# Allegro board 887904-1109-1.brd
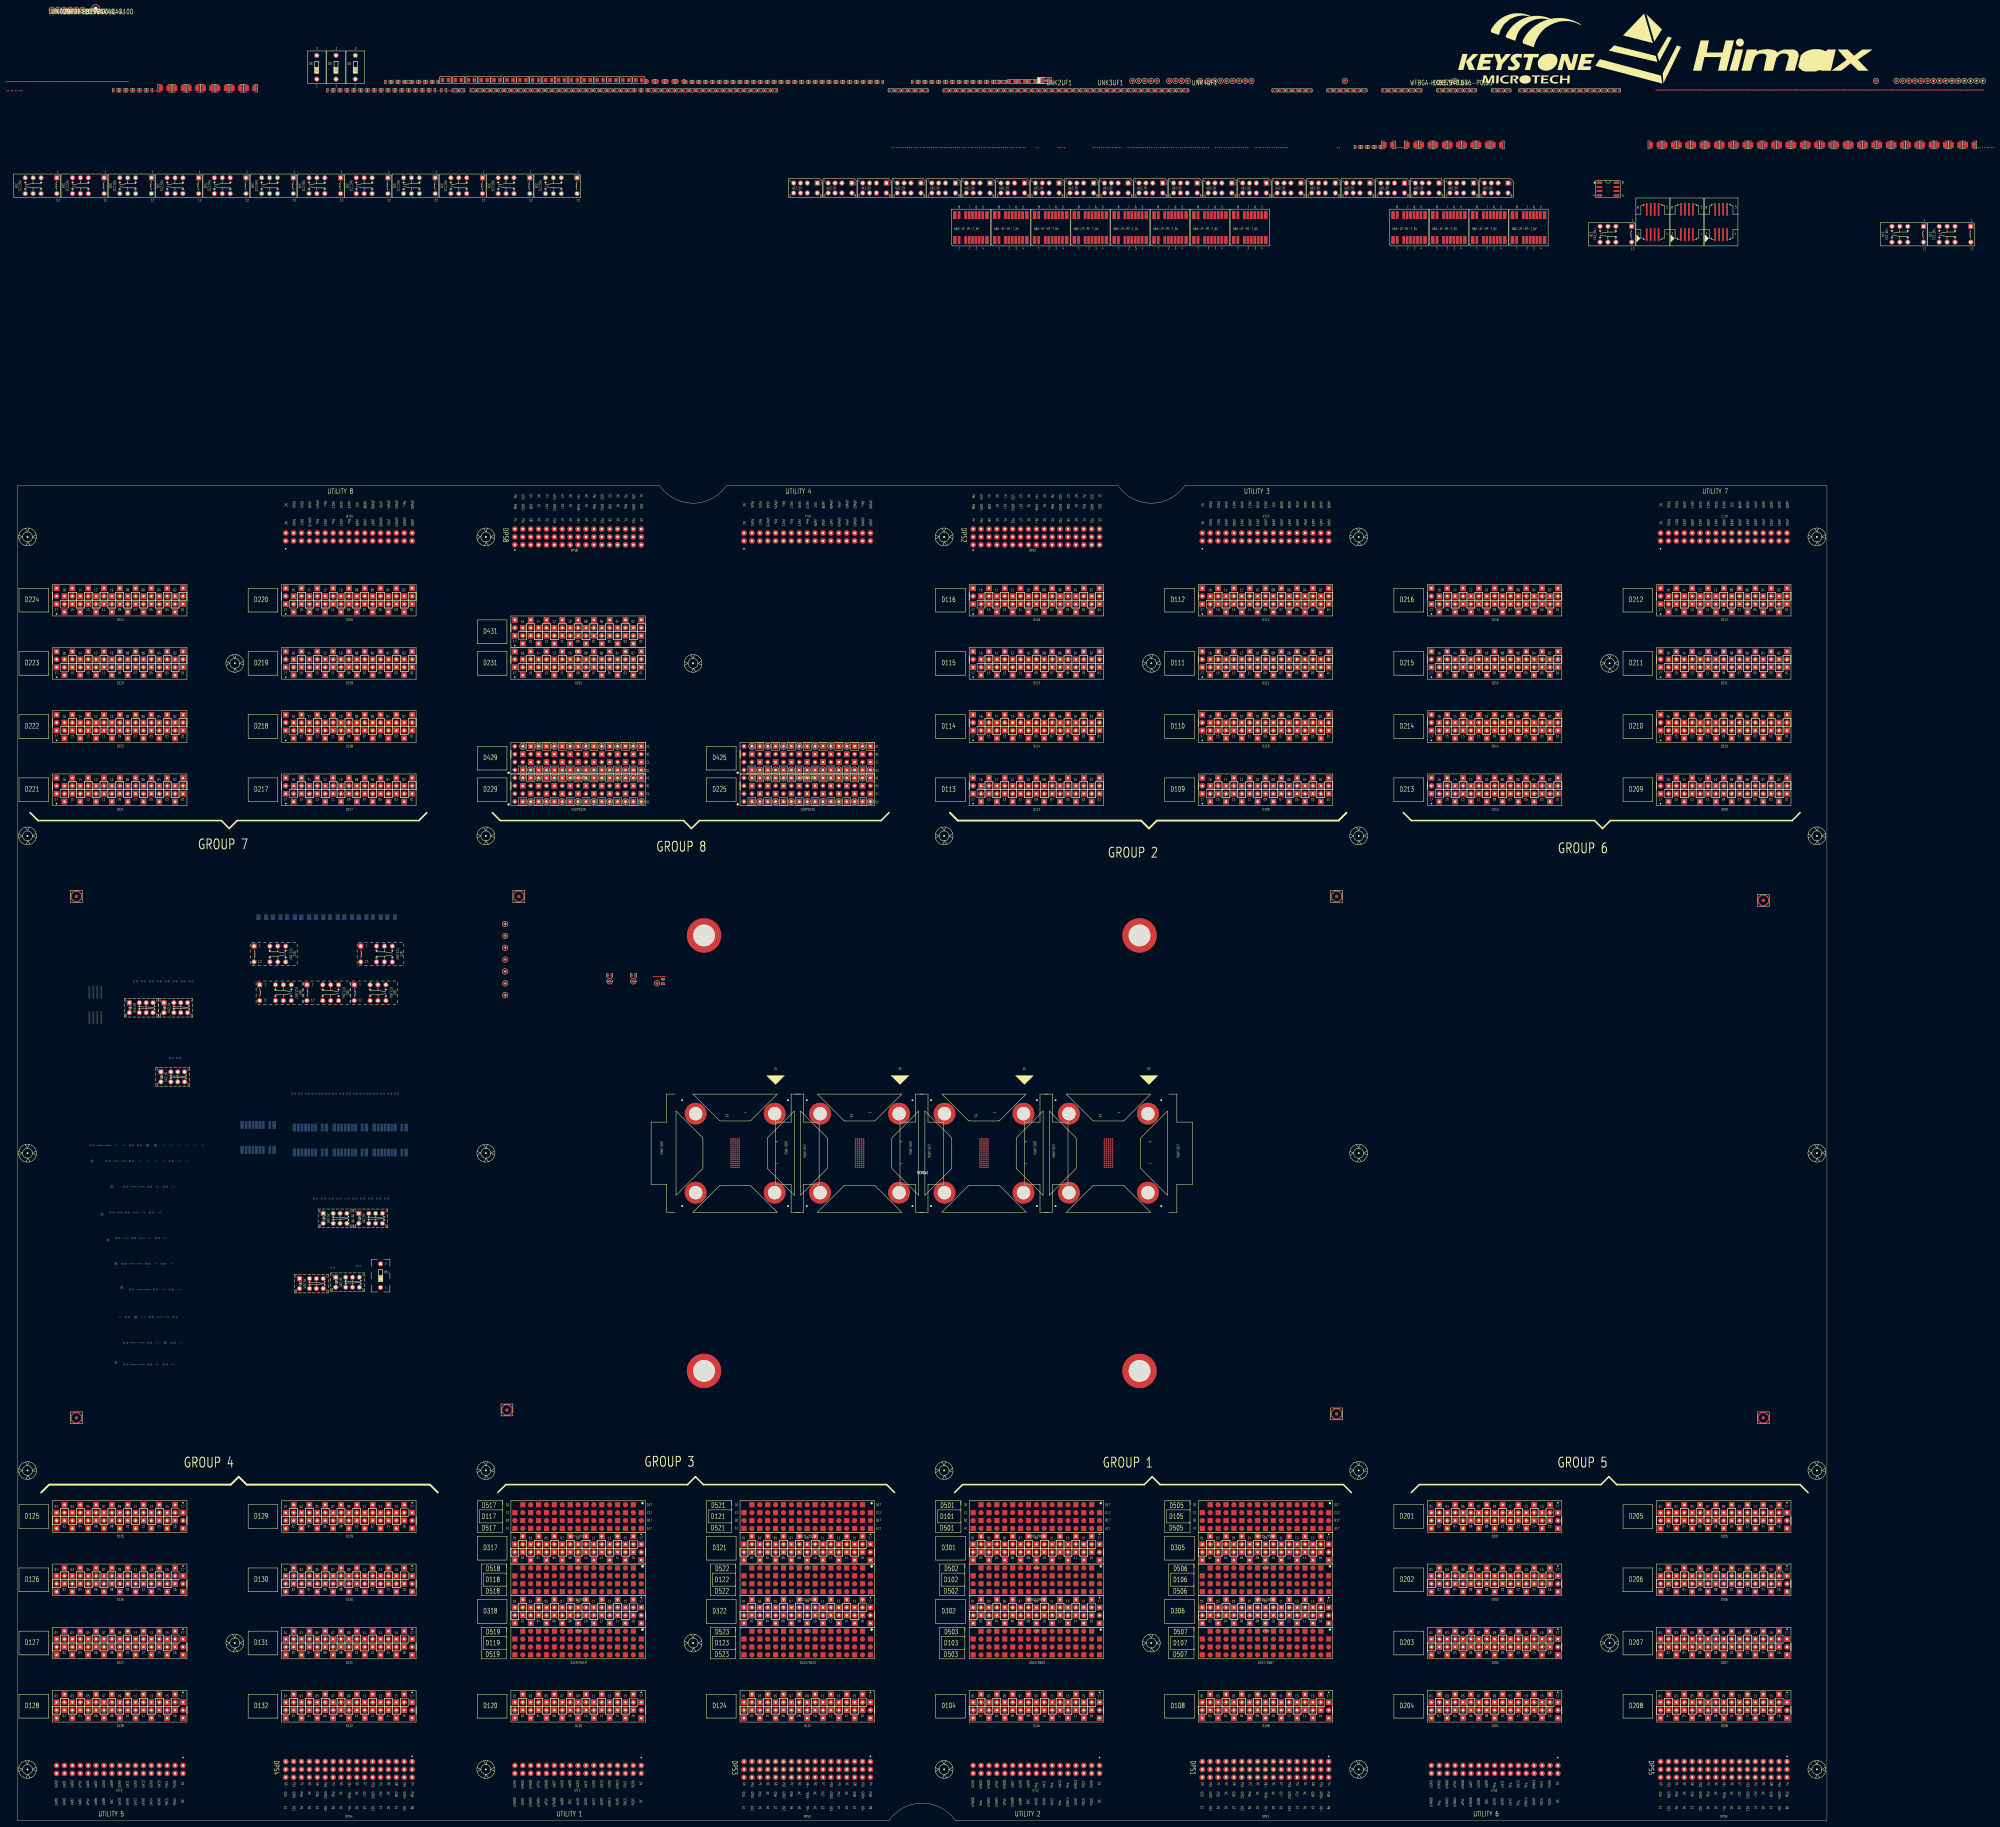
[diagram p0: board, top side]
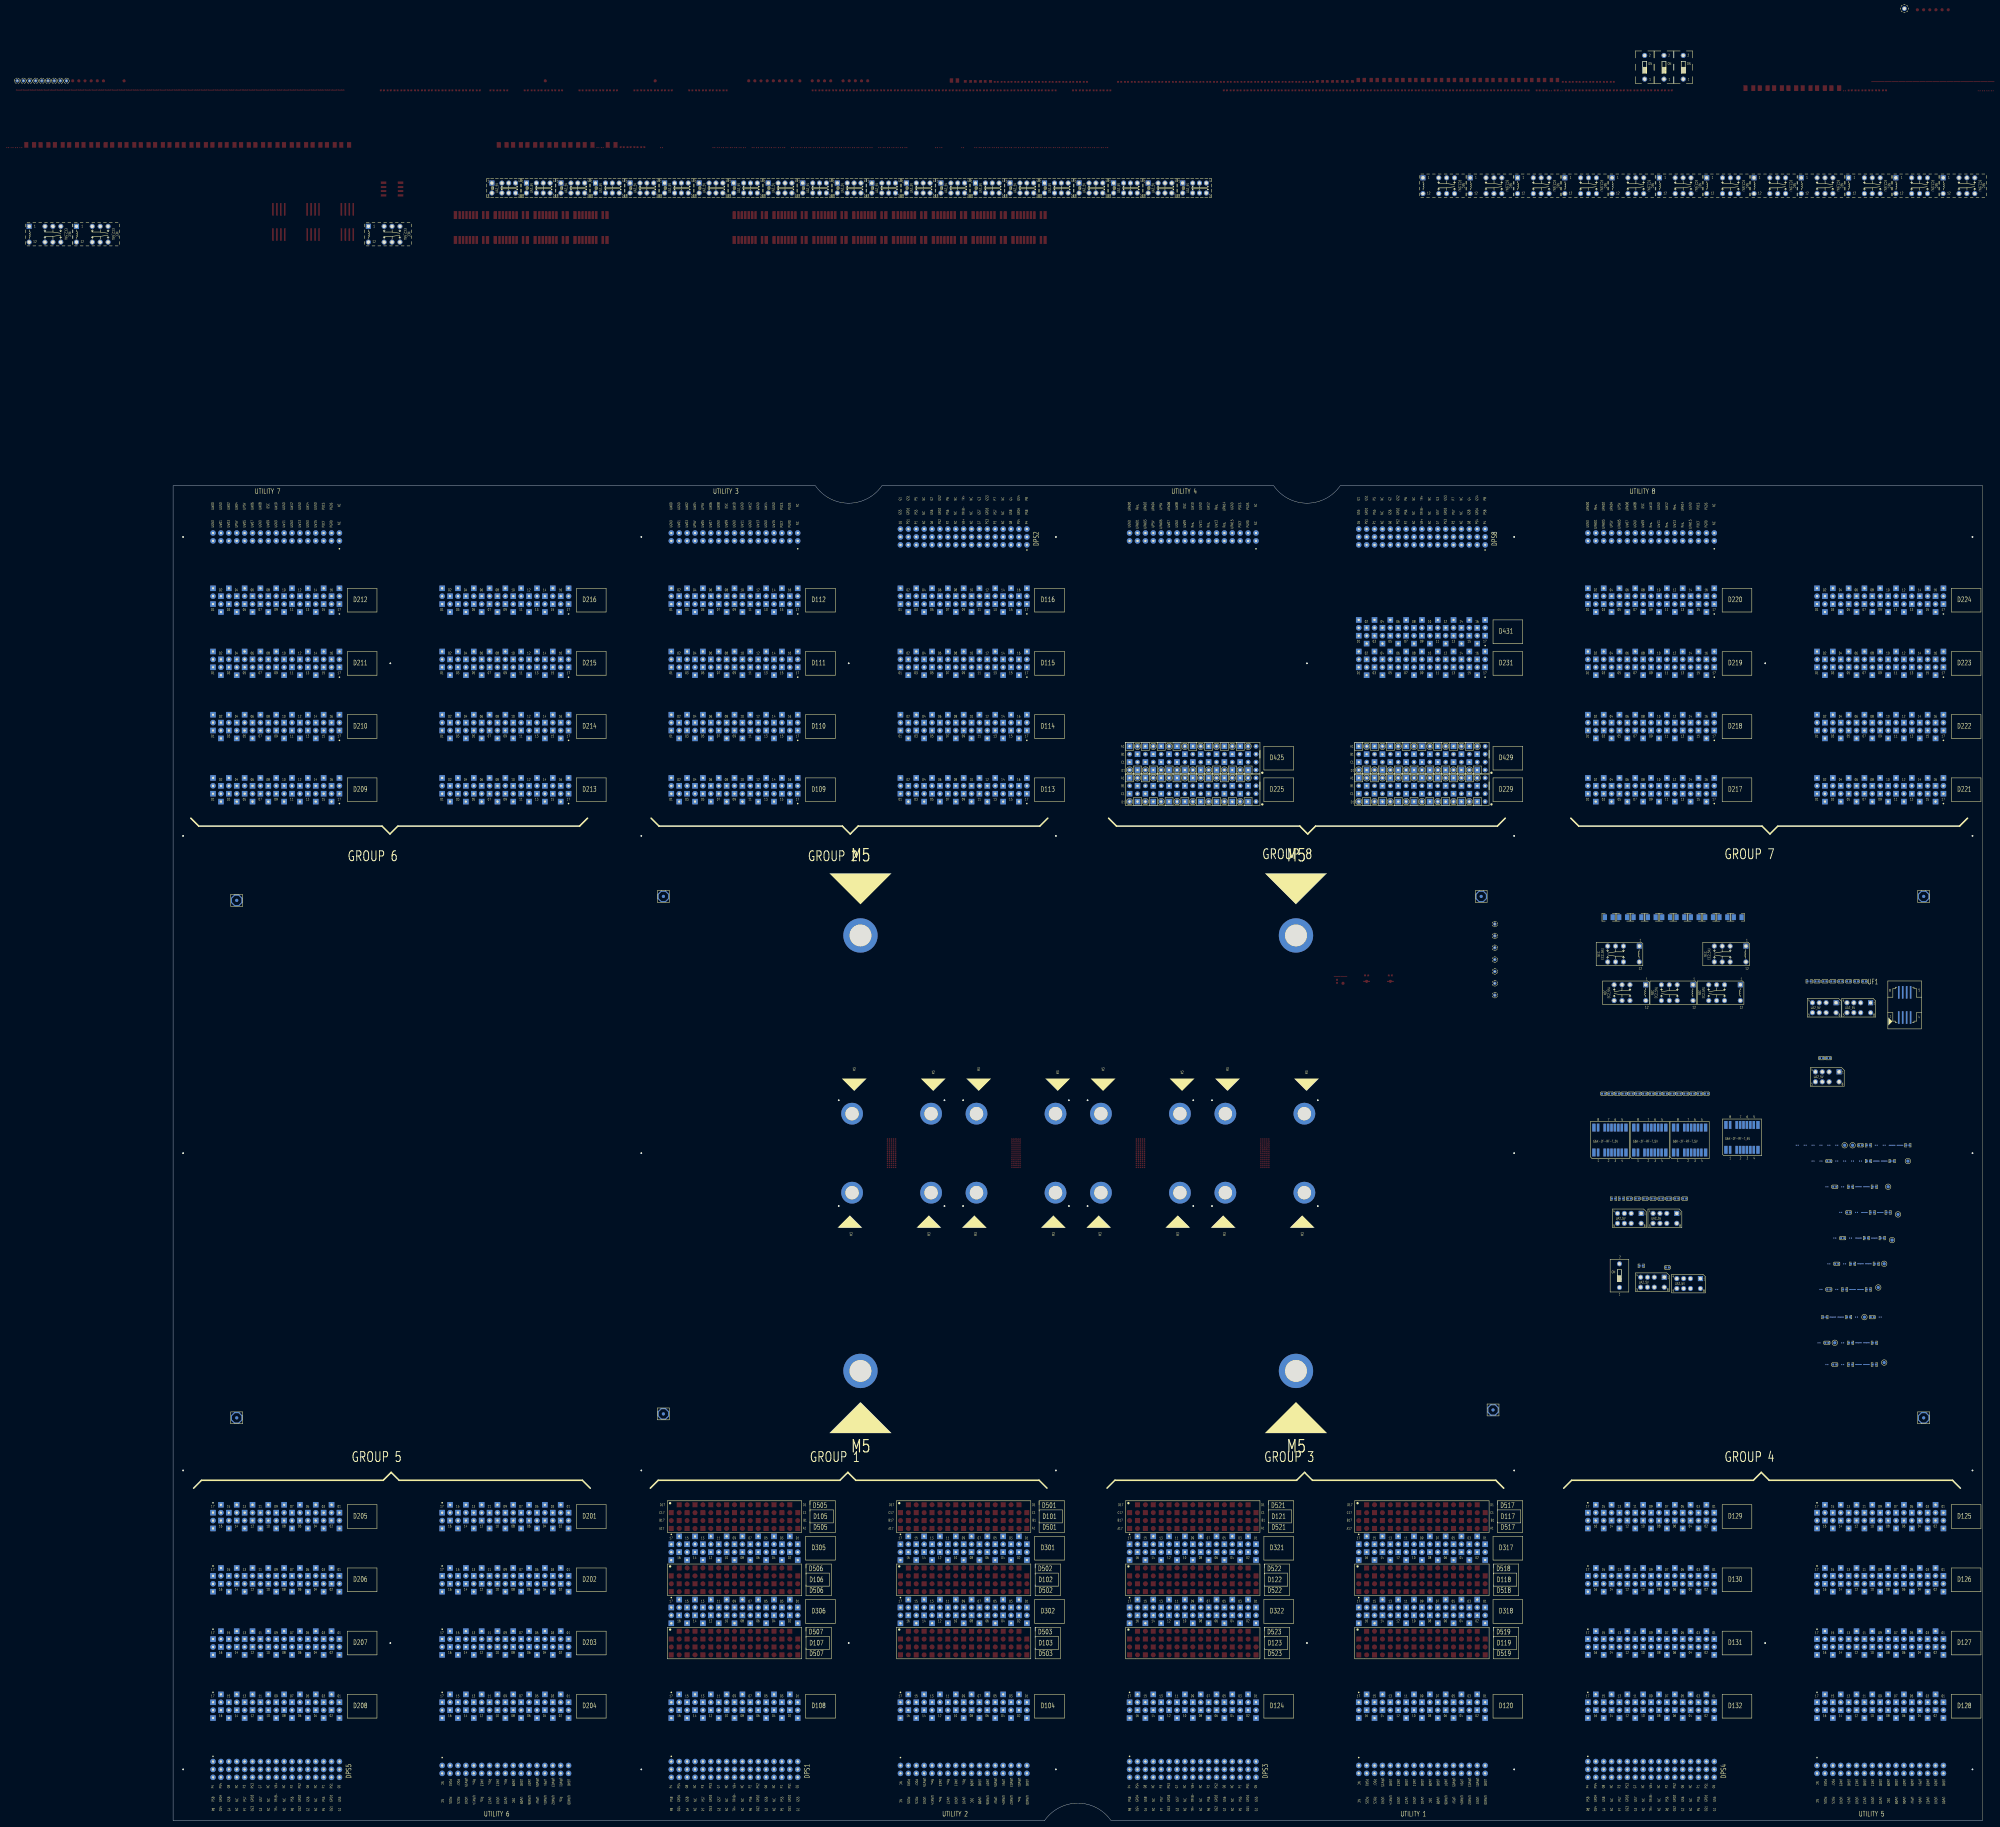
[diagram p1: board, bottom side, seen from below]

Outline 581.66 x 429.26 mm; copper layers: TOP, L02_GND, L03_SIGNAL, L04_GND, L05_SIGNAL, L06_GND, L07_SIGNAL, L08_GND, L09_POWER, L10_GND, L11_POWER, L12_GND, L13_POWER, L14_GND, L15_POWER, L16_GND, L17_POWER, L18_GND, L19_POWER, L20_GND, L21_POWER, L22_GND, L23_POWER, L24_GND, L25_5V, L26_CBIT, L27_GND, L28_SIGNAL, L29_GND, L30_SIGNAL, L31_GND, L32_SIGNAL, L33_GND, BOTTOM. Coordinates in mm from the lower left corner of the outline.

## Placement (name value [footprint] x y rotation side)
BD29  BD120-3A-S8  [FB0805]  137.61 559.64 0 top
BD30  BD120-3A-S8  [FB0805]  141.75 559.64 0 top
BD31  BD120-3A-S8  [FB0805]  145.89 559.64 0 top
BD32  BD120-3A-S8  [FB0805]  150.03 559.64 0 top
BD33  BD120-3A-S8  [FB0805]  154.17 559.64 0 top
BD34  BD120-3A-S8  [FB0805]  158.31 559.64 0 top
BD35  BD120-3A-S8  [FB0805]  162.45 559.64 0 top
BD36  BD120-3A-S8  [FB0805]  166.59 559.64 0 top
BD37  BD120-3A-S8  [FB0805]  170.73 559.64 0 top
BD38  BD120-3A-S8  [FB0805]  174.87 559.64 0 top
BD39  BD120-3A-S8  [FB0805]  179.01 559.64 0 top
BD40  BD120-3A-S8  [FB0805]  183.15 559.64 0 top
BD41  BD120-3A-S8  [FB0805]  187.29 559.64 0 top
BD42  BD120-3A-S8  [FB0805]  191.43 559.64 0 top
BD43  BD120-3A-S8  [FB0805]  195.57 559.64 0 top
BD44  BD120-3A-S8  [FB0805]  199.71 559.64 0 top
C1  0.1U-16-X-S4-MU  [C0402]  55.75 269.88 180 bottom
C53  0.1U-16-X-S4-MU  [C0402]  116.07 200.03 180 bottom
C54  0.1U-16-X-S4-MU  [C0402]  118.61 200.03 180 bottom
C55  0.1U-16-X-S4-MU  [C0402]  109.72 178.44 180 bottom
C67  1U-10-X-S4-MU  [C0402]  36.7 217.17 180 bottom
C69  10U-25-X7R-SA  [C1206]  78.7 290.49 180 bottom
C70  10U-25-X7R-SA  [C1206]  83.3 290.49 180 bottom
C71  1U-10-X-S4-MU  [C0402]  36.7 212.09 180 bottom
C73  1U-10-X-S4-MU  [C0402]  42.41 203.84 180 bottom
C75  1U-10-X-S4-MU  [C0402]  35.43 195.58 180 bottom
C77  1U-10-X-S4-MU  [C0402]  37.33 187.32 180 bottom
C79  1U-10-X-S4-MU  [C0402]  41.78 179.07 180 bottom
C81  1U-10-X-S4-MU  [C0402]  44.32 170.81 180 bottom
C83  1U-10-X-S4-MU  [C0402]  43.05 161.93 180 bottom
C85  1U-10-X-S4-MU  [C0402]  42.41 153.67 180 bottom
C87  1U-10-X-S4-MU  [C0402]  42.41 146.69 180 bottom
C89  10U-25-X7R-SA  [C1206]  87.91 290.49 180 bottom
C90  10U-25-X7R-SA  [C1206]  92.51 290.49 180 bottom
C91  10U-25-X7R-SA  [C1206]  97.11 290.49 180 bottom
C92  10U-25-X7R-SA  [C1206]  101.72 290.49 180 bottom
C93  10U-25-X7R-SA  [C1206]  106.32 290.49 180 bottom
C94  10U-25-X7R-SA  [C1206]  110.92 290.49 180 bottom
C95  10U-25-X7R-SA  [C1206]  115.53 290.49 180 bottom
C96  10U-25-X7R-SA  [C1206]  120.13 290.49 180 bottom
CA1  NC/2.2U-10-X-S4-MU  [C0402]  24 217.17 180 bottom
CA2  NC/2.2U-10-X-S4-MU  [C0402]  29.08 212.09 180 bottom
CA3  NC/2.2U-10-X-S4-MU  [C0402]  34.79 203.84 180 bottom
CA4  NC/2.2U-10-X-S4-MU  [C0402]  30.35 195.58 180 bottom
CA5  NC/2.2U-10-X-S4-MU  [C0402]  32.25 187.32 180 bottom
CA6  NC/2.2U-10-X-S4-MU  [C0402]  34.16 179.07 180 bottom
CA7  NC/2.2U-10-X-S4-MU  [C0402]  36.7 170.81 180 bottom
CA8  NC/2.2U-10-X-S4-MU  [C0402]  50.67 161.93 180 bottom
CA9  NC/2.2U-10-X-S4-MU  [C0402]  34.79 153.67 180 bottom
CA10  NC/2.2U-10-X-S4-MU  [C0402]  34.79 146.69 180 bottom
CA12  NC/2.2U-10-X-S4-MU  [C0402]  207.51 269.88 90 top
CA13  NC/2.2U-10-X-S4-MU  [C0402]  190.37 271.78 0 top
CA14  NC/2.2U-10-X-S4-MU  [C0402]  197.99 271.78 0 top
CB1  0.1U-16-X-S4-MU  [C0402]  277.38 559.05 0 top
CB2  10U-25-X7R-SA  [C1206]  457.3 538.78 0 top
CB3  0.1U-16-X-S4-MU  [C0402]  272.98 559.05 0 top
CB4  10U-25-X7R-SA  [C1206]  452.7 538.78 0 top
CB5  0.1U-16-X-S4-MU  [C0402]  270.77 559.05 0 top
CB6  10U-25-X7R-SA  [C1206]  448.09 538.78 0 top
CB7  0.1U-16-X-S4-MU  [C0402]  268.57 559.05 0 top
CB8  10U-25-X7R-SA  [C1206]  440.68 538.78 0 top
CB9  0.1U-25-X-S6  [C0603]  212.99 559.2 0 top
CB10  10U-25-X7R-SA  [C1206]  475.71 538.78 0 top
CB11  0.1U-25-X-S6  [C0603]  203.38 559.2 0 top
CB12  10U-25-X7R-SA  [C1206]  471.11 538.78 0 top
CB13  0.1U-25-X-S6  [C0603]  206.58 559.2 0 top
CB14  10U-25-X7R-SA  [C1206]  466.5 538.78 0 top
CB15  0.1U-25-X-S6  [C0603]  209.79 559.2 0 top
CB16  10U-25-X7R-SA  [C1206]  461.9 538.78 0 top
CB19  0.1U-16-X-S4-MU  [C0402]  275.18 559.05 0 top
CC1  0.47U-10-X6S-S2-TY  [C0201]  31.62 217.17 180 bottom
CC2  0.47U-10-X6S-S2-TY  [C0201]  46.86 217.17 180 bottom
CC3  0.47U-10-X6S-S2-TY  [C0201]  49.4 217.17 180 bottom
CC4  0.47U-10-X6S-S2-TY  [C0201]  34.16 217.17 180 bottom
CC5  0.47U-10-X6S-S2-TY  [C0201]  46.86 212.09 180 bottom
CC6  0.47U-10-X6S-S2-TY  [C0201]  41.78 212.09 180 bottom
CC7  0.47U-10-X6S-S2-TY  [C0201]  44.32 212.09 180 bottom
CC8  0.47U-10-X6S-S2-TY  [C0201]  44.95 203.84 180 bottom
CC9  0.47U-10-X6S-S2-TY  [C0201]  40.51 195.58 180 bottom
CC10  0.47U-10-X6S-S2-TY  [C0201]  42.41 187.32 180 bottom
CC11  0.47U-10-X6S-S2-TY  [C0201]  44.32 179.07 180 bottom
CC12  0.47U-10-X6S-S2-TY  [C0201]  46.86 170.81 180 bottom
CC13  0.47U-10-X6S-S2-TY  [C0201]  40.51 161.93 180 bottom
CC14  0.47U-10-X6S-S2-TY  [C0201]  44.95 153.67 180 bottom
CC15  0.47U-10-X6S-S2-TY  [C0201]  44.95 146.69 180 bottom
CD1  0.1U-10-X7R-S2-MU  [C0201]  51.94 217.17 180 bottom
CD2  0.1U-10-X7R-S2-MU  [C0201]  54.48 217.17 180 bottom
CD3  0.1U-10-X7R-S2-MU  [C0201]  57.02 217.17 180 bottom
CD4  0.1U-10-X7R-S2-MU  [C0201]  59.56 217.17 180 bottom
CD5  0.1U-10-X7R-S2-MU  [C0201]  51.94 212.09 180 bottom
CD6  0.1U-10-X7R-S2-MU  [C0201]  39.24 212.09 180 bottom
CD7  0.1U-10-X7R-S2-MU  [C0201]  54.48 212.09 180 bottom
CD8  0.1U-10-X7R-S2-MU  [C0201]  50.03 203.84 180 bottom
CD9  0.1U-10-X7R-S2-MU  [C0201]  45.59 195.58 180 bottom
CD10  0.1U-10-X7R-S2-MU  [C0201]  47.49 187.32 180 bottom
CD11  0.1U-10-X7R-S2-MU  [C0201]  49.4 179.07 180 bottom
CD12  0.1U-10-X7R-S2-MU  [C0201]  51.94 170.81 180 bottom
CD13  0.1U-10-X7R-S2-MU  [C0201]  32.89 161.93 180 bottom
CD14  0.1U-10-X7R-S2-MU  [C0201]  52.57 153.67 180 bottom
CD15  0.1U-10-X7R-S2-MU  [C0201]  50.03 146.69 180 bottom
CSDPS225  V93K_CSDPS_DPS32  [PG_VG93K_PF_DPS32_G8D225]  253.87 331.47 0 top
CSDPS229  V93K_CSDPS_DPS32  [PG_VG93K_PF_DPS32_G8D229]  180.21 331.47 0 top
CSDPS425  V93K_CSDPS_DPS32  [PG_VG93K_PF_DPS32_G8D425]  253.87 341.63 0 top
CSDPS429  V93K_CSDPS_DPS32  [PG_VG93K_PF_DPS32_G8D429]  180.21 341.63 0 top
D101/D501  V93K_PS1600 HD  [PG_VG93K_F_HSM_G1D101_501_ND]  327.53 97.79 0 top
D102/D502  V93K_PS1600 HD  [PG_VG93K_F_HSM_G1D102_502_ND]  327.53 77.47 0 top
D103/D503  V93K_PS1600 HD  [PG_VG93K_F_HSM_G1D103_503_ND]  327.53 57.15 0 top
D104  V93K_CH  [PG_VG93K_F_G1D104]  327.53 36.83 0 top
D105/D505  V93K_PS1600 HD  [PG_VG93K_F_HSM_G1D105_505_ND]  401.19 97.79 0 top
D106/D506  V93K_PS1600 HD  [PG_VG93K_F_HSM_G1D106_506_ND]  401.19 77.47 0 top
D107/D507  V93K_PS1600 HD  [PG_VG93K_F_HSM_G1D107_507_ND]  401.19 57.15 0 top
D108  V93K_CH  [PG_VG93K_F_G1D108]  401.19 36.83 0 top
D109  V93K_CH  [PG_VG93K_F_G2D109]  401.19 331.47 0 top
D110  V93K_CH  [PG_VG93K_F_G2D110]  401.19 351.79 0 top
D111  V93K_CH  [PG_VG93K_F_G2D111]  401.19 372.11 0 top
D112  V93K_CH  [PG_VG93K_F_G2D112]  401.19 392.43 0 top
D113  V93K_CH  [PG_VG93K_F_G2D113]  327.53 331.47 0 top
D114  V93K_CH  [PG_VG93K_F_G2D114]  327.53 351.79 0 top
D115  V93K_CH  [PG_VG93K_F_G2D115]  327.53 372.11 0 top
D116  V93K_CH  [PG_VG93K_F_G2D116]  327.53 392.43 0 top
D117/D517  V93K_PS1600 HD  [PG_VG93K_F_HSM_G3D117_517_ND]  180.21 97.79 0 top
D118/D518  V93K_PS1600 HD  [PG_VG93K_F_HSM_G3D118_518_ND]  180.21 77.47 0 top
D119/D519  V93K_PS1600 HD  [PG_VG93K_F_HSM_G3D119_519_ND]  180.21 57.15 0 top
D120  V93K_CH  [PG_VG93K_F_G3D120]  180.21 36.83 0 top
D121/D521  V93K_PS1600 HD  [PG_VG93K_F_HSM_G3D121_521_ND]  253.87 97.79 0 top
D122/D522  V93K_PS1600 HD  [PG_VG93K_F_HSM_G3D122_522_ND]  253.87 77.47 0 top
D123/D523  V93K_PS1600 HD  [PG_VG93K_F_HSM_G3D123_523_ND]  253.87 57.15 0 top
D124  V93K_CH  [PG_VG93K_F_G3D124]  253.87 36.83 0 top
D125  V93K_CH  [PG_VG93K_F_G4D125]  32.89 97.79 0 top
D126  V93K_CH  [PG_VG93K_F_G4D126]  32.89 77.47 0 top
D127  V93K_CH  [PG_VG93K_F_G4D127]  32.89 57.15 0 top
D128  V93K_CH  [PG_VG93K_F_G4D128]  32.89 36.83 0 top
D129  V93K_CH  [PG_VG93K_F_G4D129]  106.55 97.79 0 top
D130  V93K_CH  [PG_VG93K_F_G4D130]  106.55 77.47 0 top
D131  V93K_CH  [PG_VG93K_F_G4D131]  106.55 57.15 0 top
D132  V93K_CH  [PG_VG93K_F_G4D132]  106.55 36.83 0 top
D201  V93K_CH  [PG_VG93K_F_G5D201]  474.85 97.79 0 top
D202  V93K_CH  [PG_VG93K_F_G5D202]  474.85 77.47 0 top
D203  V93K_CH  [PG_VG93K_F_G5D203]  474.85 57.15 0 top
D204  V93K_CH  [PG_VG93K_F_G5D204]  474.85 36.83 0 top
D205  V93K_CH  [PG_VG93K_F_G5D205]  548.51 97.79 0 top
D206  V93K_CH  [PG_VG93K_F_G5D206]  548.51 77.47 0 top
D207  V93K_CH  [PG_VG93K_F_G5D207]  548.51 57.15 0 top
D208  V93K_CH  [PG_VG93K_F_G5D208]  548.51 36.83 0 top
D209  V93K_CH  [PG_VG93K_F_G6D209]  548.51 331.47 0 top
D210  V93K_CH  [PG_VG93K_F_G6D210]  548.51 351.79 0 top
D211  V93K_CH  [PG_VG93K_F_G6D211]  548.51 372.11 0 top
D212  V93K_CH  [PG_VG93K_F_G6D212]  548.51 392.43 0 top
D213  V93K_CH  [PG_VG93K_F_G6D213]  474.85 331.47 0 top
D214  V93K_CH  [PG_VG93K_F_G6D214]  474.85 351.79 0 top
D215  V93K_CH  [PG_VG93K_F_G6D215]  474.85 372.11 0 top
D216  V93K_CH  [PG_VG93K_F_G6D216]  474.85 392.43 0 top
D217  V93K_CH  [PG_VG93K_F_G7D217]  106.55 331.47 0 top
D218  V93K_CH  [PG_VG93K_F_G7D218]  106.55 351.79 0 top
D219  V93K_CH  [PG_VG93K_F_G7D219]  106.55 372.11 0 top
D220  V93K_CH  [PG_VG93K_F_G7D220]  106.55 392.43 0 top
D221  V93K_CH  [PG_VG93K_F_G7D221]  32.89 331.47 0 top
D222  V93K_CH  [PG_VG93K_F_G7D222]  32.89 351.79 0 top
D223  V93K_CH  [PG_VG93K_F_G7D223]  32.89 372.11 0 top
D224  V93K_CH  [PG_VG93K_F_G7D224]  32.89 392.43 0 top
D231  V93K_CH  [PG_VG93K_F_G8D231]  180.21 372.11 0 top
D301  V93K_CH  [PG_VG93K_F_G1D301]  327.53 87.63 0 top
D302  V93K_CH  [PG_VG93K_F_G1D302]  327.53 67.31 0 top
D305  V93K_CH  [PG_VG93K_F_G1D305]  401.19 87.63 0 top
D306  V93K_CH  [PG_VG93K_F_G1D306]  401.19 67.31 0 top
D317  V93K_CH  [PG_VG93K_F_G3D317]  180.21 87.63 0 top
D318  V93K_CH  [PG_VG93K_F_G3D318]  180.21 67.31 0 top
D321  V93K_CH  [PG_VG93K_F_G3D321]  253.87 87.63 0 top
D322  V93K_CH  [PG_VG93K_F_G3D322]  253.87 67.31 0 top
D431  V93K_CH  [PG_VG93K_F_G8D431]  180.21 382.27 0 top
DPS1  V93K_DPS  [PG_VG93K_F_G1DPS1]  401.19 16.51 0 top
DPS2  V93K_DPS  [PG_VG93K_F_G2DPS2]  327.53 412.75 0 top
DPS3  V93K_DPS  [PG_VG93K_F_G3DPS3]  253.87 16.51 0 top
DPS4  V93K_DPS  [PG_VG93K_F_G4DPS4]  106.55 16.51 0 top
DPS5  V93K_DPS  [PG_VG93K_F_G5DPS5]  548.51 16.51 0 top
DPS8  V93K_DPS  [PG_VG93K_F_G8DPS8]  180.21 412.75 0 top
FD1  -  [FD_040_V2]  157.35 132.08 0 top
FD2  -  [FD_040_V2]  424.05 130.81 0 top
FD3  -  [FD_040_V2]  424.05 297.18 0 top
FD4  -  [FD_040_V2]  161.16 297.18 0 top
FD5  -  [FD_040_V2]  18.92 129.54 0 top
FD6  -  [FD_040_V2]  561.21 129.54 0 top
FD7  -  [FD_040_V2]  561.21 295.91 0 top
FD8  -  [FD_040_V2]  18.92 297.18 0 top
FD9  -  [FD_040_V2]  157.35 132.08 180 bottom
FD10  -  [FD_040_V2]  424.05 130.81 180 bottom
FD11  -  [FD_040_V2]  424.05 297.18 180 bottom
FD12  -  [FD_040_V2]  161.16 297.18 180 bottom
FD13  -  [FD_040_V2]  18.92 129.54 180 bottom
FD14  -  [FD_040_V2]  561.21 129.54 180 bottom
FD15  -  [FD_040_V2]  561.21 295.91 180 bottom
FD16  -  [FD_040_V2]  18.92 297.18 180 bottom
GND1  TP01  [TP_040_T]  41.78 217.17 180 bottom
HX8879-F04  REF-CODE-CHIP  [CHIP_CODE]  460.09 558.9 0 top
K9  UA2-5NJ-A-V3  [RL_NECUA2_5V_V3]  113.33 193.68 180 bottom
K10  UA2-5NJ-A-V3  [RL_NECUA2_5V_V3]  94.28 172.72 180 bottom
K14  UA2-5NJ-A-V3  [RL_NECUA2_5V_V3]  39.57 261.4 180 bottom
K15  UA2-5NJ-A-V3  [RL_NECUA2_5V_V3]  50.68 261.4 180 bottom
K28  UA2-5NJ-A-V3  [RL_NECUA2_5V_V3]  49.72 239.18 180 bottom
K48  UA2-5NJ-A-V3  [RL_NECUA2_5V_V3]  105.9 173.14 180 bottom
K50  UA2-5NJ-A-V3  [RL_NECUA2_5V_V3]  101.9 193.68 180 bottom
K54  G6K-2F-RF-T-5V-SPECIAL  [RL_G6K2FRT_8P_5V_GR]  77.39 219.71 180 bottom
K55  EC2-5NJ-A  [RL_NECEC2_10P_5V]  84.21 266.23 180 bottom
K56  EC2-5NJ-A  [RL_NECEC2_10P_5V]  99.41 266.23 180 bottom
K57  EC2-5NJ-A  [RL_NECEC2_10P_5V]  114.61 266.23 180 bottom
K58  EC2-5NJ-A  [RL_NECEC2_10P_5V]  82.41 278.66 180 bottom
K59  EC2-5NJ-A  [RL_NECEC2_10P_5V]  116.69 278.66 180 bottom
K60  G6K-2F-RF-T-5V-SPECIAL  [RL_G6K2FRT_8P_5V_GR]  119.82 218.85 180 bottom
K61  G6K-2F-RF-T-5V-SPECIAL  [RL_G6K2FRT_8P_5V_GR]  107.01 218.85 180 bottom
K62  G6K-2F-RF-T-5V-SPECIAL  [RL_G6K2FRT_8P_5V_GR]  94.21 218.85 180 bottom
LDB1  LDB-2-S8  [LED_0805]  330.49 559.5 0 top
LOGO1  -  [LOGO_KT_KSMT]  481.96 562.84 0 top
LOGO2  LOGO_HX_Himax  [LOGO_HX_HIMAX]  550.3 564.49 0 top
LRB1  330-1-S6  [R0603]  319.75 559.2 0 top
NOREF  -  []  529.45 508.82 90 top
NOREF#2  -  []  98.72 560.45 90 top
NOREF#3  -  []  44.65 203.84 0 top
NOREF#4  -  []  335.9 516.22 0 top
NOREF#5  -  []  33.56 217.49 0 top
NOREF#6  -  []  312.8 506.32 90 top
NOREF#7  -  []  114.62 222.85 0 top
NOREF#8  -  []  321.63 538.26 0 top
NOREF#9  -  []  317.6 508.22 0 top
NOREF#10  -  []  458.82 527.93 0 top
NOREF#11  -  []  550.66 508.32 90 top
NOREF#12  -  []  314.27 521.93 90 top
NOREF#13  -  []  359.52 538.26 0 top
NOREF#14  -  []  334.83 523.33 90 top
NOREF#15  -  []  390.18 537.62 90 top
NOREF#16  -  []  332.7 195.63 90 top
NOREF#17  -  []  41.18 212.41 0 top
NOREF#18  -  []  293.37 537.62 90 top
NOREF#19  -  []  389.82 518.12 0 top
NOREF#20  -  []  101.37 216.12 90 top
NOREF#21  -  []  393.19 538.26 0 top
NOREF#22  -  []  383.81 508.22 0 top
NOREF#23  -  []  93.2 569 0 top
NOREF#24  -  []  83.01 215.26 90 top
NOREF#25  -  []  358.11 538.26 0 top
NOREF#26  -  []  380.36 537.62 90 top
NOREF#27  -  []  31.02 216.85 90 top
NOREF#28  -  []  48.8 217.49 0 top
NOREF#29  -  []  339.75 508.22 0 top
NOREF#30  -  []  229.4 219.18 0 top
NOREF#31  -  []  81.49 215.76 90 top
NOREF#32  -  []  364.81 509.49 90 top
NOREF#33  -  []  56.72 217.17 0 top
NOREF#34  -  []  -3.74 556.52 0 top
NOREF#35  -  []  105.5 192.08 90 top
NOREF#36  -  []  272 210.08 90 top
NOREF#37  -  []  362.86 508.22 90 top
NOREF#38  -  []  442.66 526.53 0 top
NOREF#39  -  []  469.72 521.93 90 top
NOREF#40  -  []  307.22 526.53 0 top
NOREF#41  -  []  466.64 518.12 0 top
NOREF#42  -  []  312.62 523.33 90 top
NOREF#43  -  []  41.18 211.77 90 top
NOREF#44  -  []  456.33 516.22 0 top
NOREF#45  -  []  260.61 526.53 0 top
NOREF#46  -  []  381.97 538.26 0 top
NOREF#47  -  []  381.1 527.93 0 top
NOREF#48  -  []  212.14 558.75 90 top
NOREF#49  -  []  392.99 537.62 90 top
NOREF#50  -  []  328.3 516.22 0 top
NOREF#51  -  []  229.4 219.18 0 top
NOREF#52  -  []  46.26 170.49 90 top
NOREF#53  -  []  289.16 537.62 90 top
NOREF#54  -  []  425.31 521.93 90 top
NOREF#55  -  []  635.42 537.62 90 top
NOREF#56  -  []  44.65 153.67 0 top
NOREF#57  -  []  262.81 526.53 0 top
NOREF#58  -  []  345.93 523.33 90 top
NOREF#59  -  []  120.37 222.85 0 top
NOREF#60  -  []  111.61 558.5 90 top
NOREF#61  -  []  98.28 174.32 0 top
NOREF#62  -  []  315.82 537.62 90 top
NOREF#63  -  []  336.15 508.27 90 top
NOREF#64  -  []  370.54 537.62 90 top
NOREF#65  -  []  460.47 526.53 0 top
NOREF#66  -  []  257.11 526.53 0 top
NOREF#67  -  []  365.43 537.94 0 top
NOREF#68  -  []  367.7 197.63 90 top
NOREF#69  -  []  352.3 537.62 90 top
NOREF#70  -  []  463.93 516.22 0 top
NOREF#71  -  []  315.72 204.55 0 top
NOREF#72  -  []  380.86 537.94 0 top
NOREF#73  -  []  465.71 507.77 90 top
NOREF#74  -  []  321.43 537.62 90 top
NOREF#75  -  []  101.9 174.74 0 top
NOREF#76  -  []  298.32 526.53 0 top
NOREF#77  -  []  454.44 509.49 90 top
NOREF#78  -  []  286.85 537.94 0 top
NOREF#79  -  []  630.31 537.94 0 top
NOREF#80  -  []  92.56 222.85 0 top
NOREF#81  -  []  304.59 537.62 90 top
NOREF#82  -  []  293.57 538.26 0 top
NOREF#83  -  []  394.42 516.22 0 top
NOREF#84  -  []  301.35 508.22 0 top
NOREF#85  -  []  336.68 527.93 0 top
NOREF#86  -  []  458.43 508.22 0 top
NOREF#87  -  []  98.31 214.9 90 top
NOREF#88  -  []  404.95 526.53 0 top
NOREF#89  -  []  348.59 537.94 0 top
NOREF#90  -  []  357.04 526.53 0 top
NOREF#91  -  []  341.1 516.22 0 top
NOREF#92  -  []  41.81 187 90 top
NOREF#93  -  []  323.04 538.26 0 top
NOREF#94  -  []  47.19 187.32 0 top
NOREF#95  -  []  288.26 537.94 0 top
NOREF#96  -  []  309.42 526.53 0 top
NOREF#97  -  []  351.4 537.94 0 top
NOREF#98  -  []  101.81 214.85 90 top
NOREF#99  -  []  279.31 526.53 0 top
NOREF#100  -  []  401.41 537.62 90 top
NOREF#101  -  []  377.55 537.62 90 top
NOREF#102  -  []  113.47 224.75 0 top
NOREF#103  -  []  22.02 267.99 0 top
NOREF#104  -  []  480.82 521.93 90 top
NOREF#105  -  []  345.48 538.26 0 top
NOREF#106  -  []  478.51 508.77 90 top
NOREF#107  -  []  47.92 240.78 0 top
NOREF#108  -  []  317.22 537.62 90 top
NOREF#109  -  []  281.17 527.93 0 top
NOREF#110  -  []  350.89 537.62 90 top
NOREF#111  -  []  368.14 526.53 0 top
NOREF#112  -  []  442.18 508.22 0 top
NOREF#113  -  []  520.25 521.72 0 top
NOREF#114  -  []  99.4 569 0 top
NOREF#115  -  []  279.31 523.33 90 top
NOREF#116  -  []  360.72 537.62 90 top
NOREF#117  -  []  243.4 201.93 90 top
NOREF#118  -  []  280.96 521.93 90 top
NOREF#119  -  []  404.95 526.53 0 top
NOREF#120  -  []  395.79 537.62 90 top
NOREF#121  -  []  480.04 509.49 90 top
NOREF#122  -  []  632.82 538.26 0 top
NOREF#123  -  []  81.14 215.71 0 top
NOREF#124  -  []  303.37 527.93 0 top
NOREF#125  -  []  528.65 508.32 90 top
NOREF#126  -  []  373.34 537.62 90 top
NOREF#127  -  []  102.4 559.94 90 top
NOREF#128  -  []  374.31 516.22 0 top
NOREF#129  -  []  343.2 508.22 0 top
NOREF#130  -  []  337.25 508.22 90 top
NOREF#131  -  []  484.04 516.22 0 top
NOREF#132  -  []  108.08 195.83 0 top
NOREF#133  -  []  347.79 527.93 0 top
NOREF#134  -  []  97.9 195.27 0 top
NOREF#135  -  []  75.74 223.71 0 top
NOREF#136  -  []  302.7 516.22 0 top
NOREF#137  -  []  25.65 266.34 0 top
NOREF#138  -  []  440.46 526.53 0 top
NOREF#139  -  []  109.33 195.27 0 top
NOREF#140  -  []  362.12 537.62 90 top
NOREF#141  -  []  118.17 222.85 0 top
NOREF#142  -  []  44.02 212.09 0 top
NOREF#143  -  []  357.01 537.94 0 top
NOREF#144  -  []  316.02 538.26 0 top
NOREF#145  -  []  33.86 217.17 0 top
NOREF#146  -  []  309.4 219.18 0 top
NOREF#147  -  []  109.9 174.74 0 top
NOREF#148  -  []  475.97 526.53 0 top
NOREF#149  -  []  346.89 538.26 0 top
NOREF#150  -  []  327.24 538.26 0 top
NOREF#151  -  []  400 537.62 90 top
NOREF#152  -  []  54.18 212.09 0 top
NOREF#153  -  []  389.61 506.32 90 top
NOREF#154  -  []  392.09 537.94 0 top
NOREF#155  -  []  293.87 537.94 0 top
NOREF#156  -  []  400.51 537.94 0 top
NOREF#157  -  []  208.94 558.75 90 top
NOREF#158  -  []  389.89 204.16 90 top
NOREF#159  -  []  93.68 567.05 0 top
NOREF#160  -  []  347.19 537.94 0 top
NOREF#161  -  []  117.07 214.85 0 top
NOREF#162  -  []  368.81 508.22 0 top
NOREF#163  -  []  46.56 212.09 0 top
NOREF#164  -  []  303.69 537.94 0 top
NOREF#165  -  []  111.13 560.45 90 top
NOREF#166  -  []  58.96 216.85 90 top
NOREF#167  -  []  116.71 171.45 90 top
NOREF#168  -  []  102.24 215.4 90 top
NOREF#169  -  []  318.33 526.53 0 top
NOREF#170  -  []  363.72 538.26 0 top
NOREF#171  -  []  376.15 537.62 90 top
NOREF#172  -  []  388.89 508.77 90 top
NOREF#173  -  []  376.81 506.32 90 top
NOREF#174  -  []  290.42 526.53 0 top
NOREF#175  -  []  375.66 508.22 90 top
NOREF#176  -  []  366.71 516.22 0 top
NOREF#177  -  []  253.7 231.63 0 top
NOREF#178  -  []  393.49 537.94 0 top
NOREF#179  -  []  355.1 537.62 90 top
NOREF#180  -  []  104.26 214.85 0 top
NOREF#181  -  []  249.51 526.53 0 top
NOREF#182  -  []  48.8 178.75 90 top
NOREF#183  -  []  89.03 169.72 90 top
NOREF#184  -  []  352.8 537.94 0 top
NOREF#185  -  []  361.51 516.22 0 top
NOREF#186  -  []  338.4 506.32 90 top
NOREF#187  -  []  88.56 216.12 90 top
NOREF#188  -  []  138.25 556.52 0 top
NOREF#189  -  []  337.68 508.77 90 top
NOREF#190  -  []  323.4 201.93 90 top
NOREF#191  -  []  384.95 526.53 0 top
NOREF#192  -  []  343.2 516.22 0 top
NOREF#193  -  []  456.33 516.22 0 top
NOREF#194  -  []  295.27 537.94 0 top
NOREF#195  -  []  291.06 537.94 0 top
NOREF#196  -  []  22.02 256.59 90 top
NOREF#197  -  []  41.48 212.09 0 top
NOREF#198  -  []  523.75 518.07 0 top
NOREF#199  -  []  48.88 263 0 top
NOREF#200  -  []  356.01 516.22 0 top
NOREF#201  -  []  361.76 508.27 90 top
NOREF#202  -  []  123.92 214.9 90 top
NOREF#203  -  []  71.74 216.98 90 top
NOREF#204  -  []  301.99 538.26 0 top
NOREF#205  -  []  376.09 508.77 90 top
NOREF#206  -  []  0.77 556.2 0 top
NOREF#207  -  []  353.7 537.62 90 top
NOREF#208  -  []  51.97 153.99 0 top
NOREF#209  -  []  384.77 538.26 0 top
NOREF#210  -  []  350.48 508.77 90 top
NOREF#211  -  []  74.64 215.71 0 top
NOREF#212  -  []  44.65 146.69 0 top
NOREF#213  -  []  309.3 537.94 0 top
NOREF#214  -  []  111.53 195.27 0 top
NOREF#215  -  []  324.24 537.62 90 top
NOREF#216  -  []  427.16 526.53 0 top
NOREF#217  -  []  247.86 527.93 0 top
NOREF#218  -  []  387.37 537.62 90 top
NOREF#219  -  []  292.07 521.93 90 top
NOREF#220  -  []  48.8 216.85 90 top
NOREF#221  -  []  33.56 216.85 90 top
NOREF#222  -  []  358.89 527.93 0 top
NOREF#223  -  []  376.35 538.26 0 top
NOREF#224  -  []  116.93 192.08 90 top
NOREF#225  -  []  348.2 279.63 90 top
NOREF#226  -  []  382.75 526.53 0 top
NOREF#227  -  []  284.05 537.94 0 top
NOREF#228  -  []  375.25 537.94 0 top
NOREF#229  -  []  332.29 558.5 90 top
NOREF#230  -  []  211.7 233.63 0 top
NOREF#231  -  []  378.06 537.94 0 top
NOREF#232  -  []  120.37 222.85 0 top
NOREF#233  -  []  403.3 527.93 0 top
NOREF#234  -  []  403.3 527.93 0 top
NOREF#235  -  []  287.22 526.53 0 top
NOREF#236  -  []  416.06 526.53 0 top
NOREF#237  -  []  289.66 537.94 0 top
NOREF#238  -  []  392.2 527.93 0 top
NOREF#239  -  []  109.33 195.27 0 top
NOREF#240  -  []  403.1 521.93 90 top
NOREF#241  -  []  296.68 537.94 0 top
NOREF#242  -  []  401.91 537.94 0 top
NOREF#243  -  []  340.7 217.09 90 top
NOREF#244  -  []  293.7 231.63 0 top
NOREF#245  -  []  203.7 204.63 90 top
NOREF#246  -  []  371.01 508.22 0 top
NOREF#247  -  []  389.28 537.94 0 top
NOREF#248  -  []  119.27 214.85 0 top
NOREF#249  -  []  452.48 508.22 90 top
NOREF#250  -  []  325.58 527.93 0 top
NOREF#251  -  []  412.53 273.64 0 top
NOREF#252  -  []  290.56 537.62 90 top
NOREF#253  -  []  369.99 527.93 0 top
NOREF#254  -  []  456.96 526.53 0 top
NOREF#255  -  []  304.8 508.22 0 top
NOREF#256  -  []  96.65 190.68 90 top
NOREF#257  -  []  399.92 516.22 0 top
NOREF#258  -  []  251.71 526.53 0 top
NOREF#259  -  []  283.75 538.26 0 top
NOREF#260  -  []  37.77 263 0 top
NOREF#261  -  []  397.7 537.94 0 top
NOREF#262  -  []  392.2 527.93 0 top
NOREF#263  -  []  39.91 195.9 0 top
NOREF#264  -  []  331.7 233.63 0 top
NOREF#265  -  []  407.52 537.94 0 top
NOREF#266  -  []  405.82 538.26 0 top
NOREF#267  -  []  105.4 558.5 90 top
NOREF#268  -  []  258.76 521.93 90 top
NOREF#269  -  []  314.62 538.26 0 top
NOREF#270  -  []  304.8 516.22 0 top
NOREF#271  -  []  335.66 538.26 0 top
NOREF#272  -  []  351.1 538.26 0 top
NOREF#273  -  []  371.64 526.53 0 top
NOREF#274  -  []  44.35 146.36 90 top
NOREF#275  -  []  102.3 195.27 0 top
NOREF#276  -  []  113.71 180.51 0 top
NOREF#277  -  []  412.55 526.53 0 top
NOREF#278  -  []  35.57 263 0 top
NOREF#279  -  []  282.82 526.53 0 top
NOREF#280  -  []  353.91 516.22 0 top
NOREF#281  -  []  235.72 204.55 0 top
NOREF#282  -  []  253.91 526.53 0 top
NOREF#283  -  []  105.9 195.27 0 top
NOREF#284  -  []  471.57 526.53 0 top
NOREF#285  -  []  346.68 537.62 90 top
NOREF#286  -  []  403.01 538.26 0 top
NOREF#287  -  []  377.01 518.12 0 top
NOREF#288  -  []  -2.34 556.52 0 top
NOREF#289  -  []  46.56 217.17 0 top
NOREF#290  -  []  452.9 508.77 90 top
NOREF#291  -  []  405.61 537.62 90 top
NOREF#292  -  []  365.13 538.26 0 top
NOREF#293  -  []  398.25 526.53 0 top
NOREF#294  -  []  293.92 526.53 0 top
NOREF#295  -  []  342.73 526.53 0 top
NOREF#296  -  []  203.7 224.63 0 top
NOREF#297  -  []  39.91 162.25 0 top
NOREF#298  -  []  447.51 521.93 90 top
NOREF#299  -  []  138.55 556.2 0 top
NOREF#300  -  []  44.47 241.33 0 top
NOREF#301  -  []  317.42 538.26 0 top
NOREF#302  -  []  100.1 195.27 0 top
NOREF#303  -  []  97.9 195.27 0 top
NOREF#304  -  []  327.7 197.63 90 top
NOREF#305  -  []  347.79 527.93 0 top
NOREF#306  -  []  345.93 526.53 0 top
NOREF#307  -  []  473.77 526.53 0 top
NOREF#308  -  []  364.21 518.12 0 top
NOREF#309  -  []  363.28 508.77 90 top
NOREF#310  -  []  179.7 258.63 0 top
NOREF#311  -  []  43.17 259.8 90 top
NOREF#312  -  []  338.33 526.53 0 top
NOREF#313  -  []  466.43 506.32 90 top
NOREF#314  -  []  31.02 217.49 0 top
NOREF#315  -  []  339.21 509.49 90 top
NOREF#316  -  []  59.26 217.17 0 top
NOREF#317  -  []  363.4 201.93 90 top
NOREF#318  -  []  34.32 258.4 90 top
NOREF#319  -  []  330.4 516.22 0 top
NOREF#320  -  []  104.1 174.74 0 top
NOREF#321  -  []  87.86 212.95 90 top
NOREF#322  -  []  479.17 526.53 0 top
NOREF#323  -  []  441.03 518.12 0 top
NOREF#324  -  []  309 538.26 0 top
NOREF#325  -  []  297.78 538.26 0 top
NOREF#326  -  []  46.26 211.77 90 top
NOREF#327  -  []  345.78 537.94 0 top
NOREF#328  -  []  491.31 508.77 90 top
NOREF#329  -  []  336.68 527.93 0 top
NOREF#330  -  []  313.01 537.62 90 top
NOREF#331  -  []  108.08 190.68 90 top
NOREF#332  -  []  113.73 195.27 0 top
NOREF#333  -  []  338 227.33 0 top
NOREF#334  -  []  299.18 538.26 0 top
NOREF#335  -  []  283.55 537.62 90 top
NOREF#336  -  []  354.2 537.94 0 top
NOREF#337  -  []  309.4 219.18 0 top
NOREF#338  -  []  248.7 233.63 0 top
NOREF#339  -  []  366.83 537.94 0 top
NOREF#340  -  []  363.52 537.62 90 top
NOREF#341  -  []  307.9 537.94 0 top
NOREF#342  -  []  149.7 315.13 0 top
NOREF#343  -  []  364.94 526.53 0 top
NOREF#344  -  []  38.94 212.09 0 top
NOREF#345  -  []  312 218.53 90 top
NOREF#346  -  []  423.66 523.33 90 top
NOREF#347  -  []  323.7 224.63 0 top
NOREF#348  -  []  296.38 538.26 0 top
NOREF#349  -  []  444.79 537.94 0 top
NOREF#350  -  []  135.84 555.88 90 top
NOREF#351  -  []  39.97 263 0 top
NOREF#352  -  []  464.87 526.53 0 top
NOREF#353  -  []  425.51 527.93 0 top
NOREF#354  -  []  46.26 212.41 0 top
NOREF#355  -  []  458.61 521.93 90 top
NOREF#356  -  []  51.08 263 0 top
NOREF#357  -  []  369.99 527.93 0 top
NOREF#358  -  []  368.81 516.22 0 top
NOREF#359  -  []  367.93 538.26 0 top
NOREF#360  -  []  268.21 523.33 90 top
NOREF#361  -  []  404.41 538.26 0 top
NOREF#362  -  []  269.4 219.18 0 top
NOREF#363  -  []  370.74 538.26 0 top
NOREF#364  -  []  46.26 171.14 0 top
NOREF#365  -  []  327.86 560.5 0 top
NOREF#366  -  []  243.7 224.63 0 top
NOREF#367  -  []  185.7 252.63 0 top
NOREF#368  -  []  469.92 527.93 0 top
NOREF#369  -  []  369.34 538.26 0 top
NOREF#370  -  []  45.72 240.78 0 top
NOREF#371  -  []  436.41 521.93 90 top
NOREF#372  -  []  379.46 537.94 0 top
NOREF#373  -  []  270.06 527.93 0 top
NOREF#374  -  []  362.32 538.26 0 top
NOREF#375  -  []  542.26 521.72 0 top
NOREF#376  -  []  303.17 521.93 90 top
NOREF#377  -  []  292.47 537.94 0 top
NOREF#378  -  []  407.22 538.26 0 top
NOREF#379  -  []  445.86 523.33 90 top
NOREF#380  -  []  381.61 516.22 0 top
NOREF#381  -  []  310.71 537.94 0 top
NOREF#382  -  []  46.68 263 0 top
NOREF#383  -  []  356.71 538.26 0 top
NOREF#384  -  []  314.48 527.93 0 top
NOREF#385  -  []  479.24 506.32 90 top
NOREF#386  -  []  377.76 538.26 0 top
NOREF#387  -  []  89.03 174.87 0 top
NOREF#388  -  []  425.51 527.93 0 top
NOREF#389  -  []  51.34 211.77 90 top
NOREF#390  -  []  633.12 537.94 0 top
NOREF#391  -  []  287.75 537.62 90 top
NOREF#392  -  []  328.7 233.63 0 top
NOREF#393  -  []  492.04 506.32 90 top
NOREF#394  -  []  134.64 556.52 0 top
NOREF#395  -  []  39.91 161.6 90 top
NOREF#396  -  []  311.65 508.22 90 top
NOREF#397  -  []  366.71 516.22 0 top
NOREF#398  -  []  391.79 538.26 0 top
NOREF#399  -  []  314.48 527.93 0 top
NOREF#400  -  []  348.09 537.62 90 top
NOREF#401  -  []  553.06 506.32 90 top
NOREF#402  -  []  534.74 509.97 90 top
NOREF#403  -  []  372.44 537.94 0 top
NOREF#404  -  []  465.28 508.22 90 top
NOREF#405  -  []  53.32 237.58 90 top
NOREF#406  -  []  394.59 538.26 0 top
NOREF#407  -  []  360.54 526.53 0 top
NOREF#408  -  []  258.96 527.93 0 top
NOREF#409  -  []  481.94 516.22 0 top
NOREF#410  -  []  305.02 526.53 0 top
NOREF#411  -  []  300.8 509.49 90 top
NOREF#412  -  []  106.09 567.05 0 top
NOREF#413  -  []  285.45 537.94 0 top
NOREF#414  -  []  32.29 162.25 0 top
NOREF#415  -  []  49.1 217.17 0 top
NOREF#416  -  []  101.9 174.74 0 top
NOREF#417  -  []  44.47 241.33 0 top
NOREF#418  -  []  89.01 222.85 0 top
NOREF#419  -  []  311.14 234.91 0 top
NOREF#420  -  []  -1.14 555.88 90 top
NOREF#421  -  []  305.99 537.62 90 top
NOREF#422  -  []  283.7 224.63 0 top
NOREF#423  -  []  310.2 537.62 90 top
NOREF#424  -  []  336.86 537.62 90 top
NOREF#425  -  []  77.94 223.71 0 top
NOREF#426  -  []  89.01 214.85 90 top
NOREF#427  -  []  341.1 516.22 0 top
NOREF#428  -  []  386.47 537.94 0 top
NOREF#429  -  []  -2.54 555.88 90 top
NOREF#430  -  []  362.62 537.94 0 top
NOREF#431  -  []  521.85 519.22 0 top
NOREF#432  -  []  338.6 518.12 0 top
NOREF#433  -  []  317.72 537.94 0 top
NOREF#434  -  []  211.7 228.68 45 top
NOREF#435  -  []  387.36 508.27 90 top
NOREF#436  -  []  379.24 523.33 90 top
NOREF#437  -  []  434.76 523.33 90 top
NOREF#438  -  []  351.64 526.53 0 top
NOREF#439  -  []  51.34 212.41 0 top
NOREF#440  -  []  382.27 537.94 0 top
NOREF#441  -  []  321.93 537.94 0 top
NOREF#442  -  []  453.76 526.53 0 top
NOREF#443  -  []  379.51 516.22 0 top
NOREF#444  -  []  333.7 231.63 0 top
NOREF#445  -  []  43.72 178.75 90 top
NOREF#446  -  []  373.55 538.26 0 top
NOREF#447  -  []  553.06 511.52 90 top
NOREF#448  -  []  357.91 537.62 90 top
NOREF#449  -  []  401.69 508.77 90 top
NOREF#450  -  []  45.43 258.4 90 top
NOREF#451  -  []  94.68 174.32 0 top
NOREF#452  -  []  32.29 161.6 90 top
NOREF#453  -  []  385.97 537.62 90 top
NOREF#454  -  []  364.92 537.62 90 top
NOREF#455  -  []  366.53 538.26 0 top
NOREF#456  -  []  386.17 538.26 0 top
NOREF#457  -  []  143.7 321.13 0 top
NOREF#458  -  []  282.65 537.94 0 top
NOREF#459  -  []  388.98 538.26 0 top
NOREF#460  -  []  349.44 526.53 0 top
NOREF#461  -  []  378.96 537.62 90 top
NOREF#462  -  []  436.61 527.93 0 top
NOREF#463  -  []  53.88 212.41 0 top
NOREF#464  -  []  531.25 521.72 0 top
NOREF#465  -  []  54.28 259.8 90 top
NOREF#466  -  []  96.65 195.83 0 top
NOREF#467  -  []  445.63 516.22 0 top
NOREF#468  -  []  326.41 509.49 90 top
NOREF#469  -  []  307.6 538.26 0 top
NOREF#470  -  []  58.96 217.49 0 top
NOREF#471  -  []  630.01 538.26 0 top
NOREF#472  -  []  350.48 507.77 90 top
NOREF#473  -  []  91.46 214.85 0 top
NOREF#474  -  []  358.89 527.93 0 top
NOREF#475  -  []  438.26 526.53 0 top
NOREF#476  -  []  632.61 537.62 90 top
NOREF#477  -  []  291.7 228.68 45 top
NOREF#478  -  []  401.69 507.77 90 top
NOREF#479  -  []  385.07 537.94 0 top
NOREF#480  -  []  390.35 523.33 90 top
NOREF#481  -  []  0.47 556.52 0 top
NOREF#482  -  []  531.05 506.32 90 top
NOREF#483  -  []  251.7 233.63 0 top
NOREF#484  -  []  49.73 203.84 0 top
NOREF#485  -  []  349.99 537.94 0 top
NOREF#486  -  []  634.22 538.26 0 top
NOREF#487  -  []  341.1 516.22 0 top
NOREF#488  -  []  443.53 516.22 0 top
NOREF#489  -  []  19.62 259.79 90 top
NOREF#490  -  []  380.89 521.93 90 top
NOREF#491  -  []  314.41 537.62 90 top
NOREF#492  -  []  438.26 526.53 0 top
NOREF#493  -  []  631.21 537.62 90 top
NOREF#494  -  []  447.71 527.93 0 top
NOREF#495  -  []  291.96 537.62 90 top
NOREF#496  -  []  269.4 219.18 0 top
NOREF#497  -  []  314.15 508.22 0 top
NOREF#498  -  []  322.83 537.62 90 top
NOREF#499  -  []  349.4 219.18 0 top
NOREF#500  -  []  402.42 506.32 90 top
NOREF#501  -  []  71.04 213.81 90 top
NOREF#502  -  []  369.64 537.94 0 top
NOREF#503  -  []  260.61 526.53 0 top
NOREF#504  -  []  19.62 254.59 90 top
NOREF#505  -  []  257.11 523.33 90 top
NOREF#506  -  []  53.88 216.85 90 top
NOREF#507  -  []  316.13 526.53 0 top
NOREF#508  -  []  320.03 537.62 90 top
NOREF#509  -  []  110.76 214.85 0 top
NOREF#510  -  []  454.98 508.22 0 top
NOREF#511  -  []  316.13 526.53 0 top
NOREF#512  -  []  353.91 516.22 0 top
NOREF#513  -  []  453.83 518.12 0 top
NOREF#514  -  []  462.67 526.53 0 top
NOREF#515  -  []  284.95 537.62 90 top
NOREF#516  -  []  72.19 223.71 0 top
NOREF#517  -  []  44.02 179.07 0 top
NOREF#518  -  []  337.68 507.77 90 top
NOREF#519  -  []  394.42 508.22 0 top
NOREF#520  -  []  371.04 537.94 0 top
NOREF#521  -  []  271.71 526.53 0 top
NOREF#522  -  []  286.55 538.26 0 top
NOREF#523  -  []  298.08 537.94 0 top
NOREF#524  -  []  51.64 217.17 0 top
NOREF#525  -  []  631.72 537.94 0 top
NOREF#526  -  []  220.7 284.63 0 top
NOREF#527  -  []  458.82 527.93 0 top
NOREF#528  -  []  479.17 523.33 90 top
NOREF#529  -  []  51.34 170.49 90 top
NOREF#530  -  []  51.34 216.85 90 top
NOREF#531  -  []  431.56 526.53 0 top
NOREF#532  -  []  38.64 211.77 90 top
NOREF#533  -  []  45.43 263.55 0 top
NOREF#534  -  []  404.21 537.62 90 top
NOREF#535  -  []  108.08 195.83 0 top
NOREF#536  -  []  325.58 527.93 0 top
NOREF#537  -  []  318.83 538.26 0 top
NOREF#538  -  []  359.31 537.62 90 top
NOREF#539  -  []  451.13 516.22 0 top
NOREF#540  -  []  476.99 508.27 90 top
NOREF#541  -  []  378.16 508.22 0 top
NOREF#542  -  []  51.64 170.81 0 top
NOREF#543  -  []  532.85 519.22 0 top
NOREF#544  -  []  265.01 526.53 0 top
NOREF#545  -  []  -2.04 556.2 0 top
NOREF#546  -  []  51.64 212.09 0 top
NOREF#547  -  []  358.69 521.93 90 top
NOREF#548  -  []  281.24 537.94 0 top
NOREF#549  -  []  338.33 526.53 0 top
NOREF#550  -  []  449.36 526.53 0 top
NOREF#551  -  []  467.79 508.22 0 top
NOREF#552  -  []  301.79 537.62 90 top
NOREF#553  -  []  44.99 195.26 90 top
NOREF#554  -  []  353.84 526.53 0 top
NOREF#555  -  []  324.87 507.77 90 top
NOREF#556  -  []  270.06 527.93 0 top
NOREF#557  -  []  44.35 153.99 0 top
NOREF#558  -  []  90.28 174.32 0 top
NOREF#559  -  []  21.22 257.09 90 top
NOREF#560  -  []  1.67 555.88 90 top
NOREF#561  -  []  283.4 201.93 90 top
NOREF#562  -  []  479.44 518.12 0 top
NOREF#563  -  []  114.17 216.12 90 top
NOREF#564  -  []  376.04 526.53 0 top
NOREF#565  -  []  331.59 558.77 90 top
NOREF#566  -  []  349.4 219.18 0 top
NOREF#567  -  []  393.85 526.53 0 top
NOREF#568  -  []  302.7 516.22 0 top
NOREF#569  -  []  312 210.08 90 top
NOREF#570  -  []  94.76 222.85 0 top
NOREF#571  -  []  35.57 263 0 top
NOREF#572  -  []  38.64 212.41 0 top
NOREF#573  -  []  272 218.53 90 top
NOREF#574  -  []  312.07 507.77 90 top
NOREF#575  -  []  401.7 170.63 90 top
NOREF#576  -  []  114.19 171.96 90 top
NOREF#577  -  []  434.76 526.53 0 top
NOREF#578  -  []  273.91 526.53 0 top
NOREF#579  -  []  34.32 263.55 0 top
NOREF#580  -  []  87.86 224.75 0 top
NOREF#581  -  []  369.13 537.62 90 top
NOREF#582  -  []  365.36 508.22 0 top
NOREF#583  -  []  76.84 215.71 0 top
NOREF#584  -  []  313 518.12 0 top
NOREF#585  -  []  539.65 508.32 90 top
NOREF#586  -  []  469.92 527.93 0 top
NOREF#587  -  []  107.56 222.85 0 top
NOREF#588  -  []  19.62 269.99 0 top
NOREF#589  -  []  453.63 506.32 90 top
NOREF#590  -  []  534.75 518.07 0 top
NOREF#591  -  []  352 210.08 90 top
NOREF#592  -  []  89.03 174.87 0 top
NOREF#593  -  []  323.1 516.22 0 top
NOREF#594  -  []  414.41 527.93 0 top
NOREF#595  -  []  318.62 537.62 90 top
NOREF#596  -  []  296.12 526.53 0 top
NOREF#597  -  []  94.76 222.85 0 top
NOREF#598  -  []  437.7 108.13 90 top
NOREF#599  -  []  489.54 516.22 0 top
NOREF#600  -  []  407.02 537.62 90 top
NOREF#601  -  []  452.9 507.77 90 top
NOREF#602  -  []  112.64 214.4 90 top
NOREF#603  -  []  51.34 217.49 0 top
NOREF#604  -  []  533.65 519.72 0 top
NOREF#605  -  []  323.35 508.27 90 top
NOREF#606  -  []  481.94 516.22 0 top
NOREF#607  -  []  298 227.33 0 top
NOREF#608  -  []  335.46 537.62 90 top
NOREF#609  -  []  313.6 509.49 90 top
NOREF#610  -  []  345.4 508.22 0 top
NOREF#611  -  []  304.79 538.26 0 top
NOREF#612  -  []  444.49 538.26 0 top
NOREF#613  -  []  46.56 170.81 0 top
NOREF#614  -  []  280.94 538.26 0 top
NOREF#615  -  []  387.15 526.53 0 top
NOREF#616  -  []  49.73 146.69 0 top
NOREF#617  -  []  469.14 516.22 0 top
NOREF#618  -  []  303.39 538.26 0 top
NOREF#619  -  []  468.07 526.53 0 top
NOREF#620  -  []  403.31 537.94 0 top
NOREF#621  -  []  393.85 526.53 0 top
NOREF#622  -  []  300.89 537.94 0 top
NOREF#623  -  []  394.89 537.94 0 top
NOREF#624  -  []  276.12 526.53 0 top
NOREF#625  -  []  331.63 526.53 0 top
NOREF#626  -  []  400.21 538.26 0 top
NOREF#627  -  []  316.32 537.94 0 top
NOREF#628  -  []  46.89 187.65 0 top
NOREF#629  -  []  408.42 537.62 90 top
NOREF#630  -  []  445.69 537.62 90 top
NOREF#631  -  []  53.72 240.78 0 top
NOREF#632  -  []  471.24 508.22 0 top
NOREF#633  -  []  443.53 516.22 0 top
NOREF#634  -  []  388.46 508.22 90 top
NOREF#635  -  []  208.7 233.63 0 top
NOREF#636  -  []  355.72 204.55 0 top
NOREF#637  -  []  302.29 537.94 0 top
NOREF#638  -  []  473.44 508.22 0 top
NOREF#639  -  []  469.14 516.22 0 top
NOREF#640  -  []  114.62 214.85 90 top
NOREF#641  -  []  392.32 516.22 0 top
NOREF#642  -  []  306.5 537.94 0 top
NOREF#643  -  []  329.39 560.22 0 top
NOREF#644  -  []  312.62 526.53 0 top
NOREF#645  -  []  99.84 214.4 90 top
NOREF#646  -  []  542.05 511.52 90 top
NOREF#647  -  []  100.65 175.29 0 top
NOREF#648  -  []  282.14 537.62 90 top
NOREF#649  -  []  374.75 537.62 90 top
NOREF#650  -  []  21.22 267.49 0 top
NOREF#651  -  []  464.18 508.27 90 top
NOREF#652  -  []  54.18 217.17 0 top
NOREF#653  -  []  287.7 197.63 90 top
NOREF#654  -  []  44.35 203.51 90 top
NOREF#655  -  []  324.45 508.22 90 top
NOREF#656  -  []  379.51 516.22 0 top
NOREF#657  -  []  377.62 509.49 90 top
NOREF#658  -  []  349.44 526.53 0 top
NOREF#659  -  []  360.92 538.26 0 top
NOREF#660  -  []  56.42 216.85 90 top
NOREF#661  -  []  251.7 228.68 45 top
NOREF#662  -  []  373.84 526.53 0 top
NOREF#663  -  []  356.01 508.22 0 top
NOREF#664  -  []  447.71 527.93 0 top
NOREF#665  -  []  400.17 508.27 90 top
NOREF#666  -  []  32.59 161.93 0 top
NOREF#667  -  []  103.16 222.85 0 top
NOREF#668  -  []  447.83 508.22 0 top
NOREF#669  -  []  42.11 187.32 0 top
NOREF#670  -  []  471.57 526.53 0 top
NOREF#671  -  []  114.19 178.56 0 top
NOREF#672  -  []  418.26 526.53 0 top
NOREF#673  -  []  366.71 516.22 0 top
NOREF#674  -  []  296.17 537.62 90 top
NOREF#675  -  []  54.68 263 0 top
NOREF#676  -  []  467.24 509.49 90 top
NOREF#677  -  []  634.02 537.62 90 top
NOREF#678  -  []  292.27 527.93 0 top
NOREF#679  -  []  109.5 171.54 90 top
NOREF#680  -  []  52.27 153.67 0 top
NOREF#681  -  []  291.7 233.63 0 top
NOREF#682  -  []  531.05 511.52 90 top
NOREF#683  -  []  484.04 508.22 0 top
NOREF#684  -  []  424.06 538.26 0 top
NOREF#685  -  []  290.76 538.26 0 top
NOREF#686  -  []  285.02 526.53 0 top
NOREF#687  -  []  476.74 516.22 0 top
NOREF#688  -  []  72.61 216.26 90 top
NOREF#689  -  []  281.17 527.93 0 top
NOREF#690  -  []  349.69 538.26 0 top
NOREF#691  -  []  443.39 537.94 0 top
NOREF#692  -  []  387.58 538.26 0 top
NOREF#693  -  []  406.12 537.94 0 top
NOREF#694  -  []  310.41 538.26 0 top
NOREF#695  -  []  329.43 526.53 0 top
NOREF#696  -  []  0.27 555.88 90 top
NOREF#697  -  []  360.7 144.63 90 top
NOREF#698  -  []  388.89 507.77 90 top
NOREF#699  -  []  327.54 537.94 0 top
NOREF#700  -  []  348.2 279.63 0 top
NOREF#701  -  []  429.36 526.53 0 top
NOREF#702  -  []  424.36 537.94 0 top
NOREF#703  -  []  327.23 526.53 0 top
NOREF#704  -  []  53.88 211.77 90 top
NOREF#705  -  []  312.07 508.77 90 top
NOREF#706  -  []  294.77 537.62 90 top
NOREF#707  -  []  106.46 214.85 0 top
NOREF#708  -  []  282.35 538.26 0 top
NOREF#709  -  []  44.99 195.9 0 top
NOREF#710  -  []  258 227.33 0 top
NOREF#711  -  []  369.79 521.93 90 top
NOREF#712  -  []  382.75 526.53 0 top
NOREF#713  -  []  324.87 508.77 90 top
NOREF#714  -  []  41.81 187.65 0 top
NOREF#715  -  []  125.44 214.4 90 top
NOREF#716  -  []  90.36 222.85 0 top
NOREF#717  -  []  372.7 195.63 90 top
NOREF#718  -  []  49.43 146.36 90 top
NOREF#719  -  []  90.28 174.32 0 top
NOREF#720  -  []  353.9 538.26 0 top
NOREF#721  -  []  93.66 214.85 0 top
NOREF#722  -  []  73.54 223.71 0 top
NOREF#723  -  []  271.71 526.53 0 top
NOREF#724  -  []  351.2 506.32 90 top
NOREF#725  -  []  46.89 187 90 top
NOREF#726  -  []  425.26 537.62 90 top
NOREF#727  -  []  247.86 527.93 0 top
NOREF#728  -  []  373.85 537.94 0 top
NOREF#729  -  []  340.53 526.53 0 top
NOREF#730  -  []  392 521.93 90 top
NOREF#731  -  []  401.45 523.33 90 top
NOREF#732  -  []  401.61 538.26 0 top
NOREF#733  -  []  287.96 538.26 0 top
NOREF#734  -  []  358.41 537.94 0 top
NOREF#735  -  []  348.29 538.26 0 top
NOREF#736  -  []  371.94 537.62 90 top
NOREF#737  -  []  232 218.53 90 top
NOREF#738  -  []  374.95 538.26 0 top
NOREF#739  -  []  101.81 222.85 0 top
NOREF#740  -  []  349.14 227.66 0 top
NOREF#741  -  []  451.56 526.53 0 top
NOREF#742  -  []  460.63 508.22 0 top
NOREF#743  -  []  44.35 204.16 0 top
NOREF#744  -  []  320.53 537.94 0 top
NOREF#745  -  []  542.05 506.32 90 top
NOREF#746  -  []  202.53 558.75 90 top
NOREF#747  -  []  327.23 526.53 0 top
NOREF#748  -  []  134.94 556.2 0 top
NOREF#749  -  []  319.8 508.22 0 top
NOREF#750  -  []  325.6 506.32 90 top
NOREF#751  -  []  332.6 508.22 0 top
NOREF#752  -  []  302.7 516.22 0 top
NOREF#753  -  []  371.64 526.53 0 top
NOREF#754  -  []  319.13 537.94 0 top
NOREF#755  -  []  252.7 195.63 90 top
NOREF#756  -  []  326.95 508.22 0 top
NOREF#757  -  []  300.38 537.62 90 top
NOREF#758  -  []  313.51 537.94 0 top
NOREF#759  -  []  323.7 204.63 90 top
NOREF#760  -  []  301.52 523.33 90 top
NOREF#761  -  []  379.51 516.22 0 top
NOREF#762  -  []  46.26 217.49 0 top
NOREF#763  -  []  391.58 537.62 90 top
NOREF#764  -  []  358.21 508.22 0 top
NOREF#765  -  []  40.21 195.58 0 top
NOREF#766  -  []  100.66 224.75 0 top
NOREF#767  -  []  381.61 508.22 0 top
NOREF#768  -  []  315.5 516.22 0 top
NOREF#769  -  []  307.4 537.62 90 top
NOREF#770  -  []  31.32 217.17 0 top
NOREF#771  -  []  364.02 537.94 0 top
NOREF#772  -  []  292.7 195.63 90 top
NOREF#773  -  []  523.74 509.97 90 top
NOREF#774  -  []  368.14 523.33 90 top
NOREF#775  -  []  100.66 212.95 90 top
NOREF#776  -  []  49.43 203.51 90 top
NOREF#777  -  []  545.75 509.97 90 top
NOREF#778  -  []  111.11 214.9 90 top
NOREF#779  -  []  480.59 508.22 0 top
NOREF#780  -  []  420.46 526.53 0 top
NOREF#781  -  []  51.97 153.35 90 top
NOREF#782  -  []  43.72 211.77 90 top
NOREF#783  -  []  334.83 526.53 0 top
NOREF#784  -  []  46.68 263 0 top
NOREF#785  -  []  115.04 215.4 90 top
NOREF#786  -  []  294.97 538.26 0 top
NOREF#787  -  []  402.81 537.62 90 top
NOREF#788  -  []  292.17 538.26 0 top
NOREF#789  -  []  414.41 527.93 0 top
NOREF#790  -  []  387.11 516.22 0 top
NOREF#791  -  []  478.09 508.22 90 top
NOREF#792  -  []  247.7 197.63 90 top
NOREF#793  -  []  443.09 538.26 0 top
NOREF#794  -  []  395.7 176.63 90 top
NOREF#795  -  []  449.36 526.53 0 top
NOREF#796  -  []  43.72 179.39 0 top
NOREF#797  -  []  77.94 223.71 0 top
NOREF#798  -  []  282.82 526.53 0 top
NOREF#799  -  []  334.26 538.26 0 top
NOREF#800  -  []  348.7 516.22 0 top
NOREF#801  -  []  336.48 521.93 90 top
NOREF#802  -  []  290.42 523.33 90 top
NOREF#803  -  []  374.56 508.27 90 top
NOREF#804  -  []  43.72 212.41 0 top
NOREF#805  -  []  249.51 526.53 0 top
NOREF#806  -  []  50.12 240.78 0 top
NOREF#807  -  []  543.86 519.22 0 top
NOREF#808  -  []  331.7 228.68 45 top
NOREF#809  -  []  311.61 537.62 90 top
NOREF#810  -  []  99.88 567.05 0 top
NOREF#811  -  []  46.26 216.85 90 top
NOREF#812  -  []  308.8 537.62 90 top
NOREF#813  -  []  456.33 516.22 0 top
NOREF#814  -  []  350.05 508.22 90 top
NOREF#815  -  []  258.96 527.93 0 top
NOREF#816  -  []  317.6 516.22 0 top
NOREF#817  -  []  353.91 516.22 0 top
NOREF#818  -  []  390.42 509.49 90 top
NOREF#819  -  []  368.23 537.94 0 top
NOREF#820  -  []  366.33 537.62 90 top
NOREF#821  -  []  335.96 537.94 0 top
NOREF#822  -  []  315.5 516.22 0 top
NOREF#823  -  []  300.2 518.12 0 top
NOREF#824  -  []  314.92 537.94 0 top
NOREF#825  -  []  49.1 179.07 0 top
NOREF#826  -  []  445.86 526.53 0 top
NOREF#827  -  []  285.15 538.26 0 top
NOREF#828  -  []  40.21 161.93 0 top
NOREF#829  -  []  445.63 508.22 0 top
NOREF#830  -  []  458.43 516.22 0 top
NOREF#831  -  []  397.4 538.26 0 top
NOREF#832  -  []  522.65 519.72 0 top
NOREF#833  -  []  367.73 537.62 90 top
NOREF#834  -  []  392.32 516.22 0 top
NOREF#835  -  []  544.66 519.72 0 top
NOREF#836  -  []  328.3 516.22 0 top
NOREF#837  -  []  108.61 559.94 90 top
NOREF#838  -  []  444.29 537.62 90 top
NOREF#839  -  []  396.05 526.53 0 top
NOREF#840  -  []  361.22 537.94 0 top
NOREF#841  -  []  45.29 195.58 0 top
NOREF#842  -  []  105.61 569 0 top
NOREF#843  -  []  352.5 538.26 0 top
NOREF#844  -  []  107.56 222.85 0 top
NOREF#845  -  []  293.92 526.53 0 top
NOREF#846  -  []  407.15 526.53 0 top
NOREF#847  -  []  320.23 538.26 0 top
NOREF#848  -  []  44.35 147.01 0 top
NOREF#849  -  []  303.37 527.93 0 top
NOREF#850  -  []  218 227.33 0 top
NOREF#851  -  []  289.36 538.26 0 top
NOREF#852  -  []  486.24 508.22 0 top
NOREF#853  -  []  351.41 518.12 0 top
NOREF#854  -  []  468.07 523.33 90 top
NOREF#855  -  []  44.47 236.18 90 top
NOREF#856  -  []  634.52 537.94 0 top
NOREF#857  -  []  56.42 217.49 0 top
NOREF#858  -  []  311.81 538.26 0 top
NOREF#859  -  []  306.2 538.26 0 top
NOREF#860  -  []  205.73 558.75 90 top
NOREF#861  -  []  44.03 556.2 0 top
NOREF#862  -  []  45.43 263.55 0 top
NOREF#863  -  []  379.24 526.53 0 top
NOREF#864  -  []  330.4 508.22 0 top
NOREF#865  -  []  48.8 179.39 0 top
NOREF#866  -  []  123.57 214.85 0 top
NOREF#867  -  []  348.95 508.27 90 top
NOREF#868  -  []  49.43 147.01 0 top
NOREF#869  -  []  392.32 516.22 0 top
NOREF#870  -  []  288.7 233.63 0 top
NOREF#871  -  []  297.58 537.62 90 top
NOREF#872  -  []  315.5 516.22 0 top
NOREF#873  -  []  352 218.53 90 top
NOREF#874  -  []  489.79 508.27 90 top
NOREF#875  -  []  49.43 204.16 0 top
NOREF#876  -  []  305.09 537.94 0 top
NOREF#877  -  []  416.06 526.53 0 top
NOREF#878  -  []  113.47 212.95 90 top
NOREF#879  -  []  436.61 527.93 0 top
NOREF#880  -  []  357.04 523.33 90 top
NOREF#881  -  []  390.68 537.94 0 top
NOREF#882  -  []  43.57 263 0 top
NOREF#883  -  []  404.71 537.94 0 top
NOREF#884  -  []  313.21 538.26 0 top
NOREF#885  -  []  311.14 196.91 90 top
NOREF#886  -  []  390.97 508.22 0 top
NOREF#887  -  []  376.65 537.94 0 top
NOREF#888  -  []  106.3 174.74 0 top
NOREF#889  -  []  104.92 560.45 90 top
NOREF#890  -  []  443.53 516.22 0 top
NOREF#891  -  []  349.49 537.62 90 top
NOREF#892  -  []  396.62 508.22 0 top
NOREF#893  -  []  43.73 556.52 0 top
NOREF#894  -  []  301.52 526.53 0 top
NOREF#895  -  []  394.39 537.62 90 top
NOREF#896  -  []  390.38 538.26 0 top
NOREF#897  -  []  401.27 508.22 90 top
NOREF#898  -  []  275.72 204.55 0 top
NOREF#899  -  []  325.38 521.93 90 top
NOREF#900  -  []  352.01 509.49 90 top
NOREF#901  -  []  -3.44 556.2 0 top
NOREF#902  -  []  469.14 516.22 0 top
NOREF#903  -  []  213.7 231.63 0 top
NOREF#904  -  []  268.21 526.53 0 top
NOREF#905  -  []  491.31 507.77 90 top
NOREF#906  -  []  460.47 526.53 0 top
NOREF#907  -  []  323.34 537.94 0 top
NOREF#908  -  []  299.48 537.94 0 top
NOREF#909  -  []  292.27 527.93 0 top
NOREF#910  -  []  39.91 195.26 90 top
NOREF#911  -  []  26.93 258.24 90 top
NOREF#912  -  []  -0.63 556.2 0 top
NOREF#913  -  []  97.88 171.12 90 top
NOREF#914  -  []  465.71 508.77 90 top
NOREF#915  -  []  300.59 538.26 0 top
NOREF#916  -  []  323.73 523.33 90 top
NOREF#917  -  []  139.45 555.88 90 top
NOREF#918  -  []  323.73 526.53 0 top
NOREF#919  -  []  328.3 516.22 0 top
NOREF#920  -  []  113.71 170.01 90 top
NOREF#921  -  []  360.54 526.53 0 top
NOREF#922  -  []  325.8 518.12 0 top
NOREF#923  -  []  44.35 153.35 90 top
NOREF#924  -  []  92.48 174.32 0 top
NOREF#925  -  []  387.88 537.94 0 top
NOREF#926  -  []  363.28 507.77 90 top
NOREF#927  -  []  540.45 508.82 90 top
NOREF#928  -  []  -0.93 556.52 0 top
NOREF#929  -  []  481.94 516.22 0 top
NOREF#930  -  []  362.74 526.53 0 top
NOREF#931  -  []  347.58 521.93 90 top
NOREF#932  -  []  372.14 538.26 0 top
NOREF#933  -  []  310.55 508.27 90 top
NOREF#934  -  []  89.44 215.4 90 top
NOREF#935  -  []  53.88 217.49 0 top
NOREF#936  -  []  45.72 240.78 0 top
NOREF#937  -  []  310.3 516.22 0 top
NOREF#938  -  []  96.2 559.94 90 top
NOREF#939  -  []  490.89 508.22 90 top
NOREF#940  -  []  398.8 538.26 0 top
NOREF#941  -  []  398.6 537.62 90 top
NOREF#942  -  []  631.42 538.26 0 top
NOREF#943  -  []  478.51 507.77 90 top
NOREF#944  -  []  359.82 537.94 0 top
NOREF#945  -  []  414.2 521.93 90 top
NOREF#946  -  []  243.7 204.63 90 top
NOREF#947  -  []  376.09 507.77 90 top
NOREF#948  -  []  51.34 171.14 0 top
NOREF#949  -  []  105.36 222.85 0 top
NOREF#950  -  []  320.53 526.53 0 top
NOREF#951  -  []  305.02 526.53 0 top
NOREF#952  -  []  34.32 263.55 0 top
NOREF#953  -  []  399.1 537.94 0 top
NOREF#954  -  []  220.7 217.09 90 top
NOREF#955  -  []  303.19 537.62 90 top
NOREF#956  -  []  115.97 222.85 0 top
NOREF#957  -  []  312.11 537.94 0 top
NOREF#958  -  []  97.96 214.85 0 top
NOREF#959  -  []  72.19 215.71 90 top
NOREF#960  -  []  286.35 537.62 90 top
NOREF#961  -  []  352.56 508.22 0 top
NOREF#962  -  []  551.46 508.82 90 top
NOREF#963  -  []  381.1 527.93 0 top
NOREF#964  -  []  99.2 558.5 90 top
NOREF#965  -  []  364.01 506.32 90 top
NOREF#966  -  []  117.33 195.27 0 top
NOREF#967  -  []  334.56 537.94 0 top
NOREF#968  -  []  260.7 217.09 90 top
NOREF#969  -  []  328.44 537.62 90 top
NOREF#970  -  []  307 508.22 0 top
NOREF#971  -  []  283.7 204.63 90 top
NOREF#972  -  []  412.55 523.33 90 top
NOREF#973  -  []  380.56 538.26 0 top
NOREF#974  -  []  71.04 225.61 0 top
NOREF#975  -  []  379.16 538.26 0 top
NOREF#976  -  []  300.7 217.09 90 top
NOREF#977  -  []  451.38 508.27 90 top
NOREF#978  -  []  427.16 526.53 0 top
NOREF#979  -  []  381.76 537.62 90 top
NOREF#980  -  []  423.66 526.53 0 top
NOREF#981  -  []  44.93 555.88 90 top
NOREF#982  -  []  409.35 526.53 0 top
NOREF#983  -  []  545.76 518.07 0 top
NOREF#984  -  []  456.96 523.33 90 top
NOREF#985  -  []  232 210.08 90 top
NOREF#986  -  []  383.17 537.62 90 top
NOREF#987  -  []  390.35 526.53 0 top
NOREF#988  -  []  401.45 526.53 0 top
NOREF#989  -  []  298.98 537.62 90 top
NOREF#990  -  []  269.86 521.93 90 top
